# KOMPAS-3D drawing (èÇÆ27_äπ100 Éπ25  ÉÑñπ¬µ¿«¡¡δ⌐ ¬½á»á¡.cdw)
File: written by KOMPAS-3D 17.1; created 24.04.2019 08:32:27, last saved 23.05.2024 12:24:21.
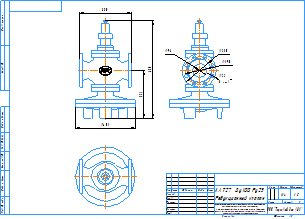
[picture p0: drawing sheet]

Sheet 1: A3, landscape

Title block, sheet 1: name: КАТ27  Ду100 Ру25 / Редукционный клапан; material: Сталь 20  ГОСТ 1050-88; mass: 114; sheets: 1; sheet format: A3; stored path: D:\Документы\Компас\Поставщики\Armstrong\Редукционный клапан GP-2000\KOMPAS 2D\GP-2000 _ Ду100 Ру25  Редукционный клапан.cdw

Views: Вид 1
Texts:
  adm
  Рама для чертежей
  Лит-Масса-Масштаб
  Материал-Предприятие
  Масштаб
  Изм.
  Лист
  № докум.
  Подп.
  Дата
  Лит.
  Разраб.
  Пров.
  Т.контр.
  Листов
  Внимание! Данный продукт является объектом авторского права ООО «Торговый Дом АДЛ».
  Запрещается изменение, копирование, распространение
  (в том числе путем копирования на другие сайты и ресурсы в Интернете)
  или любое иное использование информации и объектов без предварительного
  согласия правообладателя (ООО «Торговый Дом АДЛ»).
  Н.контр.
  Утв.
  ООО "Торговый дом АДЛ"
  Изменение
  Номер документа
  Подпись
  Обозначение документа
  Наименование изделия
  Масса изделия по ГОСТ 2.109-73
  Порядковый номер листа
  Общее количество листов в документе
  Характер работы, выполненной лицом, подписавшим документ
  Наименование или индекс предприятия, выпускающего документ
  Инв. № подл.
  Подп. и дата
  Взам. инв. №
  Инв. № дубл.
  Инвентарный номер подлинника по ГОСТ 2.501-68
  Подпись принявшего подлинник в отдел технической документации
  Инвентарный номер подлинника, взамен которого выпущен данный подлинник
  Инвентарный номер дубликата по ГОСТ 2.502-68
  Подпись принявшего дубликат в отдел технической документации
  Справ. №
  Перв. примен.
  Обозначение документа, взамен или на основании которого выпущен данный документ
  Обозначение документа, в котором впервые записан данный документ
  Подпись лица, копировавшего чертеж
  Обозначение формата листа
  !Рама для чертежа
Dimensions and other numbers on the sheet: 350; 321; 658; 401; 230; 190; 22; 8 отв.; 96; 1:5; 1; 114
